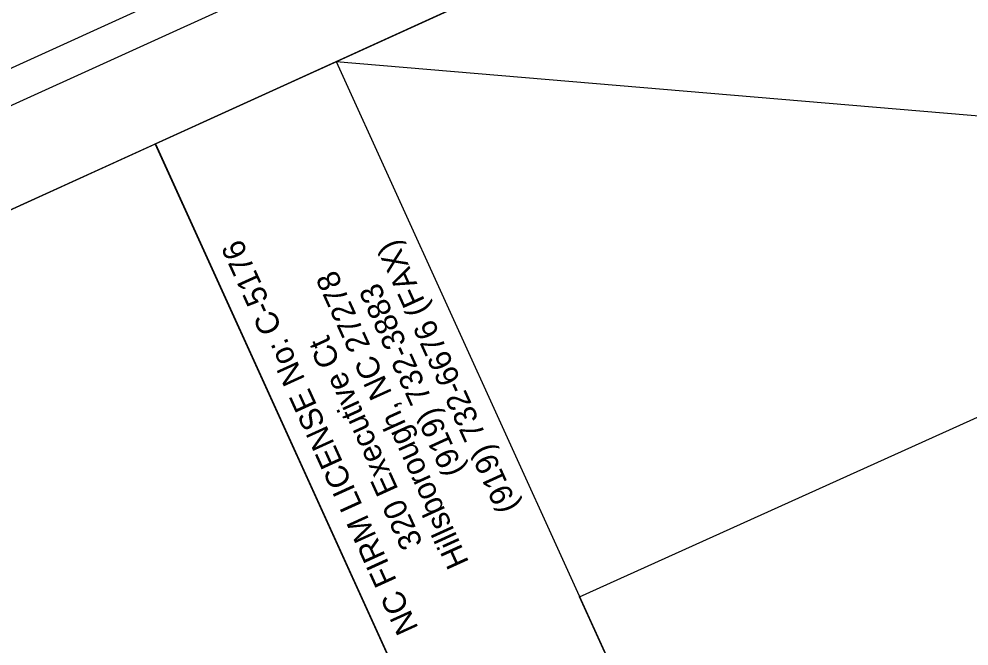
# Model space of a CAD drawing. Extents: x 2097233 to 2098987, y 683915 to 686009.
# Drawn here: x 2097438.9 to 2097564.4, y 685437 to 685519.9 of the extents above; entities that cross this region are included whole.
import ezdxf

# ---------------------------------------------------------------- set-up
doc = ezdxf.new("R2010")
doc.units = 0
for name, color, linetype in [('Scratch_Level_6', 7, 'Continuous'), ('Sheet Block Title CELL', 7, 'Continuous'), ('Sheet Layout Plan Border', 7, 'Continuous'), ('Sheet Plan CELL', 7, 'Continuous'), ('Sheet Plot Border Inside CELL', 7, 'Continuous'), ('Sheet Plot Border Outside CELL', 7, 'Continuous')]:
    doc.layers.add(name, color=color, linetype=linetype)

msp = doc.modelspace()

# ---------------------------------------------------------------- linework, layer by layer
at = {"layer": 'Scratch_Level_6'}
msp.add_line((2097640.09, 685500.72), (2097480.77, 685514.22), dxfattribs=at)
at = {"layer": 'Sheet Block Title CELL'}
msp.add_lwpolyline([(2097539.72, 685321.27), (2097456.86, 685503.36), (2097480.76, 685514.24), (2097563.62, 685332.14)], close=True, dxfattribs=at)
at = {"layer": 'Sheet Layout Plan Border'}
msp.add_lwpolyline([(2098897.26, 684510.8), (2097955.44, 684082.23), (2097499.89, 685083.35), (2097523.79, 685094.22), (2097440.93, 685276.32), (2097563.62, 685332.14), (2097512.93, 685443.54), (2098309.25, 685803.01)], close=True, dxfattribs=at)
at = {"layer": 'Sheet Plan CELL'}
for points in [[(2097320.28, 685441.22), (2097941.56, 684075.89), (2098897.27, 684510.77), (2098276, 685876.08)], [(2098897.27, 684510.77), (2097941.59, 684075.88), (2097403.14, 685259.11), (2097539.72, 685321.27), (2097456.88, 685503.35), (2098276, 685876.08)], [(2097395.9, 685365.73), (2097354.48, 685456.74), (2097456.88, 685503.35), (2097498.31, 685412.33)]]:
    msp.add_lwpolyline(points, close=True, dxfattribs=at)
at = {"layer": 'Sheet Plot Border Inside CELL'}
msp.add_lwpolyline([(2098963.13, 684372.11), (2098273.1, 685888.48), (2097312.85, 685451.54), (2098002.87, 683935.16)], close=True, dxfattribs=at)
at = {"layer": 'Sheet Plot Border Outside CELL'}
msp.add_lwpolyline([(2098986.71, 684368.56), (2098289.45, 685900.88), (2097292.78, 685447.36), (2097990.05, 683915.04)], close=True, dxfattribs=at)

# ---------------------------------------------------------------- texts
at = {"layer": 'Sheet Block Title CELL'}
for s, p in [('NC FIRM LICENSE No: C-5176', (2097491.68, 685439.39)), ('(919) 732-6676 (FAX)', (2097504.92, 685455.41)), ('Hillsborough, NC 27278', (2097498.36, 685448.09)), ('(919) 732-3883', (2097497.78, 685460.23)), ('320 Executive Ct', (2097492.27, 685450.61))]:
    msp.add_text(s, height=3.0009, rotation=114.4674, dxfattribs=at).set_placement(p)

doc.saveas('drawing.dxf')
